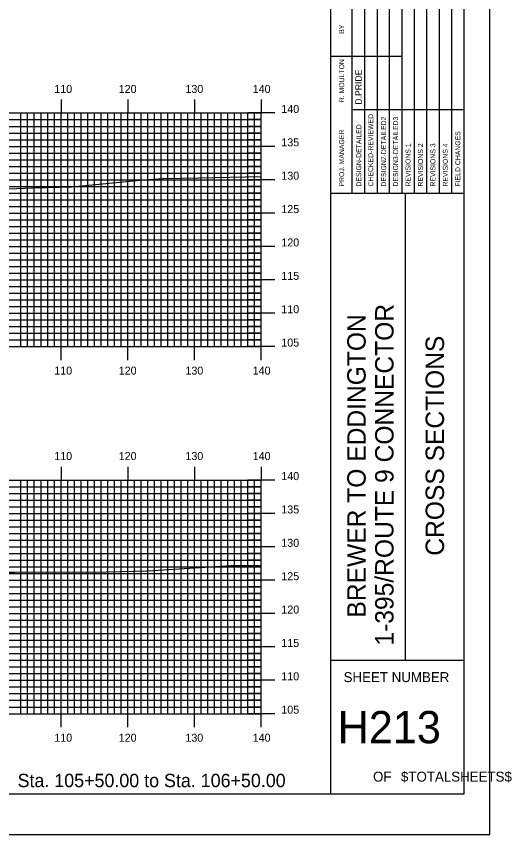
# Model space of a CAD drawing. Extents: x 1768087 to 1768430, y 442591 to 442811.
# Drawn here: x 1768356.3 to 1768430.5, y 442590.5 to 442713.1 of the extents above; entities that cross this region are included whole.
import ezdxf

# ---------------------------------------------------------------- set-up
doc = ezdxf.new("R2010")
doc.units = 0
for name, color, linetype in [('BORDER', 7, 'Continuous'), ('H_V ANNOTATION', 7, 'Continuous'), ('MAJOR', 7, 'Continuous'), ('MINOR', 7, 'Continuous'), ('PLOT BOUNDARY', 7, 'Continuous'), ('S_Roadway_Centerline', 7, 'Continuous')]:
    doc.layers.add(name, color=color, linetype=linetype)

msp = doc.modelspace()

# ---------------------------------------------------------------- linework, layer by layer
at = {"layer": 'BORDER'}
for p, q in [((1768403.36, 442596.67), (1768403.36, 442806.67)), ((1768403.36, 442686.67), (1768423.36, 442686.67)), ((1768414.54, 442616.67), (1768414.54, 442686.67)), ((1768403.36, 442616.67), (1768423.36, 442616.67))]:
    msp.add_line(p, q, dxfattribs=at)
msp.add_lwpolyline([(1768103.36, 442596.67), (1768423.36, 442596.67), (1768423.36, 442806.67), (1768103.36, 442806.67)], close=True, dxfattribs=at)
for points in [[(1768408.46, 442686.68), (1768408.46, 442721.67)], [(1768410.32, 442721.67), (1768410.32, 442686.68)], [(1768412.18, 442686.68), (1768412.18, 442721.67)], [(1768414.05, 442686.68), (1768414.05, 442721.67)], [(1768415.91, 442686.68), (1768415.91, 442721.67)], [(1768417.77, 442686.68), (1768417.77, 442721.67)], [(1768419.64, 442686.68), (1768419.64, 442721.67)], [(1768421.5, 442686.68), (1768421.5, 442721.67)], [(1768406.59, 442686.68), (1768406.59, 442720.26)], [(1768403.36, 442707.17), (1768406.59, 442707.17)], [(1768406.59, 442707.17), (1768414.05, 442707.17)], [(1768406.59, 442699.17), (1768423.36, 442699.17)]]:
    msp.add_lwpolyline(points, dxfattribs=at)
at = {"layer": 'MAJOR'}
for p, q in [((1768362.96, 442700.67), (1768362.96, 442698.67)), ((1768372.96, 442700.67), (1768372.96, 442698.67)), ((1768382.96, 442700.67), (1768382.96, 442698.67)), ((1768392.96, 442700.67), (1768392.96, 442698.67)), ((1768112.96, 442698.67), (1768392.96, 442698.67)), ((1768112.96, 442698.67), (1768392.96, 442698.67)), ((1768362.96, 442663.67), (1768362.96, 442698.67)), ((1768372.96, 442663.67), (1768372.96, 442698.67)), ((1768382.96, 442663.67), (1768382.96, 442698.67)), ((1768394.97, 442698.67), (1768390.96, 442698.67)), ((1768392.96, 442663.67), (1768392.96, 442698.67)), ((1768392.96, 442663.67), (1768392.96, 442698.67)), ((1768112.96, 442693.67), (1768392.96, 442693.67)), ((1768394.97, 442693.67), (1768390.96, 442693.67)), ((1768112.96, 442688.67), (1768392.96, 442688.67)), ((1768394.97, 442688.67), (1768390.96, 442688.67)), ((1768112.96, 442683.67), (1768392.96, 442683.67)), ((1768394.97, 442683.67), (1768390.96, 442683.67)), ((1768112.96, 442678.67), (1768392.96, 442678.67)), ((1768394.97, 442678.67), (1768390.96, 442678.67)), ((1768112.96, 442673.67), (1768392.96, 442673.67)), ((1768394.97, 442673.67), (1768390.96, 442673.67)), ((1768112.96, 442668.67), (1768392.96, 442668.67)), ((1768394.97, 442668.67), (1768390.96, 442668.67)), ((1768112.96, 442663.67), (1768392.96, 442663.67)), ((1768112.96, 442663.67), (1768392.96, 442663.67)), ((1768362.96, 442661.66), (1768362.96, 442663.67)), ((1768372.96, 442661.66), (1768372.96, 442663.67)), ((1768382.96, 442661.66), (1768382.96, 442663.67)), ((1768394.97, 442663.67), (1768390.96, 442663.67)), ((1768392.96, 442661.66), (1768392.96, 442663.67)), ((1768362.96, 442645.67), (1768362.96, 442643.67)), ((1768372.96, 442645.67), (1768372.96, 442643.67)), ((1768382.96, 442645.67), (1768382.96, 442643.67)), ((1768392.96, 442645.67), (1768392.96, 442643.67)), ((1768112.96, 442643.67), (1768392.96, 442643.67)), ((1768112.96, 442643.67), (1768392.96, 442643.67)), ((1768362.96, 442608.67), (1768362.96, 442643.67)), ((1768372.96, 442608.67), (1768372.96, 442643.67)), ((1768382.96, 442608.67), (1768382.96, 442643.67)), ((1768394.97, 442643.67), (1768390.96, 442643.67)), ((1768392.96, 442608.67), (1768392.96, 442643.67)), ((1768392.96, 442608.67), (1768392.96, 442643.67)), ((1768112.96, 442638.67), (1768392.96, 442638.67)), ((1768394.97, 442638.67), (1768390.96, 442638.67)), ((1768112.96, 442633.67), (1768392.96, 442633.67)), ((1768394.97, 442633.67), (1768390.96, 442633.67)), ((1768112.96, 442628.67), (1768392.96, 442628.67)), ((1768394.97, 442628.67), (1768390.96, 442628.67)), ((1768112.96, 442623.67), (1768392.96, 442623.67)), ((1768394.97, 442623.67), (1768390.96, 442623.67)), ((1768112.96, 442618.67), (1768392.96, 442618.67)), ((1768394.97, 442618.67), (1768390.96, 442618.67)), ((1768112.96, 442613.67), (1768392.96, 442613.67)), ((1768394.97, 442613.67), (1768390.96, 442613.67)), ((1768112.96, 442608.67), (1768392.96, 442608.67)), ((1768112.96, 442608.67), (1768392.96, 442608.67)), ((1768362.96, 442606.66), (1768362.96, 442608.67)), ((1768372.96, 442606.66), (1768372.96, 442608.67)), ((1768382.96, 442606.66), (1768382.96, 442608.67)), ((1768394.97, 442608.67), (1768390.96, 442608.67)), ((1768392.96, 442606.66), (1768392.96, 442608.67))]:
    msp.add_line(p, q, dxfattribs=at)
at = {"layer": 'MINOR'}
for p, q in [((1768356.96, 442663.67), (1768356.96, 442698.67)), ((1768357.96, 442663.67), (1768357.96, 442698.67)), ((1768358.96, 442663.67), (1768358.96, 442698.67)), ((1768359.96, 442663.67), (1768359.96, 442698.67)), ((1768360.96, 442663.67), (1768360.96, 442698.67)), ((1768361.96, 442663.67), (1768361.96, 442698.67)), ((1768363.96, 442663.67), (1768363.96, 442698.67)), ((1768364.96, 442663.67), (1768364.96, 442698.67)), ((1768365.96, 442663.67), (1768365.96, 442698.67)), ((1768366.96, 442663.67), (1768366.96, 442698.67)), ((1768367.96, 442663.67), (1768367.96, 442698.67)), ((1768368.96, 442663.67), (1768368.96, 442698.67)), ((1768369.96, 442663.67), (1768369.96, 442698.67)), ((1768370.96, 442663.67), (1768370.96, 442698.67)), ((1768371.96, 442663.67), (1768371.96, 442698.67)), ((1768373.96, 442663.67), (1768373.96, 442698.67)), ((1768374.96, 442663.67), (1768374.96, 442698.67)), ((1768375.96, 442663.67), (1768375.96, 442698.67)), ((1768376.96, 442663.67), (1768376.96, 442698.67)), ((1768377.96, 442663.67), (1768377.96, 442698.67)), ((1768378.96, 442663.67), (1768378.96, 442698.67)), ((1768379.96, 442663.67), (1768379.96, 442698.67)), ((1768380.96, 442663.67), (1768380.96, 442698.67)), ((1768381.96, 442663.67), (1768381.96, 442698.67)), ((1768383.96, 442663.67), (1768383.96, 442698.67)), ((1768384.96, 442663.67), (1768384.96, 442698.67)), ((1768385.96, 442663.67), (1768385.96, 442698.67)), ((1768386.96, 442663.67), (1768386.96, 442698.67)), ((1768387.96, 442663.67), (1768387.96, 442698.67)), ((1768388.96, 442663.67), (1768388.96, 442698.67)), ((1768389.96, 442663.67), (1768389.96, 442698.67)), ((1768390.96, 442663.67), (1768390.96, 442698.67)), ((1768391.96, 442663.67), (1768391.96, 442698.67)), ((1768112.96, 442697.67), (1768392.96, 442697.67)), ((1768112.96, 442696.67), (1768392.96, 442696.67)), ((1768392.96, 442697.67), (1768390.96, 442697.67)), ((1768392.96, 442696.67), (1768390.96, 442696.67)), ((1768112.96, 442695.67), (1768392.96, 442695.67)), ((1768392.96, 442695.67), (1768390.96, 442695.67)), ((1768112.96, 442694.67), (1768392.96, 442694.67)), ((1768392.96, 442694.67), (1768390.96, 442694.67)), ((1768112.96, 442692.67), (1768392.96, 442692.67)), ((1768392.96, 442692.67), (1768390.96, 442692.67)), ((1768112.96, 442691.67), (1768392.96, 442691.67)), ((1768112.96, 442690.67), (1768392.96, 442690.67)), ((1768392.96, 442691.67), (1768390.96, 442691.67)), ((1768392.96, 442690.67), (1768390.96, 442690.67)), ((1768112.96, 442689.67), (1768392.96, 442689.67)), ((1768392.96, 442689.67), (1768390.96, 442689.67)), ((1768112.96, 442687.67), (1768392.96, 442687.67)), ((1768392.96, 442687.67), (1768390.96, 442687.67)), ((1768112.96, 442686.67), (1768392.96, 442686.67)), ((1768112.96, 442685.67), (1768392.96, 442685.67)), ((1768392.96, 442686.67), (1768390.96, 442686.67)), ((1768392.96, 442685.67), (1768390.96, 442685.67)), ((1768112.96, 442684.67), (1768392.96, 442684.67)), ((1768392.96, 442684.67), (1768390.96, 442684.67)), ((1768112.96, 442682.67), (1768392.96, 442682.67)), ((1768392.96, 442682.67), (1768390.96, 442682.67)), ((1768112.96, 442681.67), (1768392.96, 442681.67)), ((1768392.96, 442681.67), (1768390.96, 442681.67)), ((1768112.96, 442680.67), (1768392.96, 442680.67)), ((1768112.96, 442679.67), (1768392.96, 442679.67)), ((1768392.96, 442680.67), (1768390.96, 442680.67)), ((1768392.96, 442679.67), (1768390.96, 442679.67)), ((1768112.96, 442677.67), (1768392.96, 442677.67)), ((1768392.96, 442677.67), (1768390.96, 442677.67)), ((1768112.96, 442676.67), (1768392.96, 442676.67)), ((1768392.96, 442676.67), (1768390.96, 442676.67)), ((1768112.96, 442675.67), (1768392.96, 442675.67)), ((1768112.96, 442674.67), (1768392.96, 442674.67)), ((1768392.96, 442675.67), (1768390.96, 442675.67)), ((1768392.96, 442674.67), (1768390.96, 442674.67)), ((1768112.96, 442672.67), (1768392.96, 442672.67)), ((1768392.96, 442672.67), (1768390.96, 442672.67)), ((1768112.96, 442671.67), (1768392.96, 442671.67)), ((1768392.96, 442671.67), (1768390.96, 442671.67)), ((1768112.96, 442670.67), (1768392.96, 442670.67)), ((1768112.96, 442669.67), (1768392.96, 442669.67)), ((1768392.96, 442670.67), (1768390.96, 442670.67)), ((1768392.96, 442669.67), (1768390.96, 442669.67)), ((1768112.96, 442667.67), (1768392.96, 442667.67)), ((1768392.96, 442667.67), (1768390.96, 442667.67)), ((1768112.96, 442666.67), (1768392.96, 442666.67)), ((1768392.96, 442666.67), (1768390.96, 442666.67)), ((1768112.96, 442665.67), (1768392.96, 442665.67)), ((1768392.96, 442665.67), (1768390.96, 442665.67)), ((1768112.96, 442664.67), (1768392.96, 442664.67)), ((1768392.96, 442664.67), (1768390.96, 442664.67)), ((1768356.96, 442608.67), (1768356.96, 442643.67)), ((1768357.96, 442608.67), (1768357.96, 442643.67)), ((1768358.96, 442608.67), (1768358.96, 442643.67)), ((1768359.96, 442608.67), (1768359.96, 442643.67)), ((1768360.96, 442608.67), (1768360.96, 442643.67)), ((1768361.96, 442608.67), (1768361.96, 442643.67)), ((1768363.96, 442608.67), (1768363.96, 442643.67)), ((1768364.96, 442608.67), (1768364.96, 442643.67)), ((1768365.96, 442608.67), (1768365.96, 442643.67)), ((1768366.96, 442608.67), (1768366.96, 442643.67)), ((1768367.96, 442608.67), (1768367.96, 442643.67)), ((1768368.96, 442608.67), (1768368.96, 442643.67)), ((1768369.96, 442608.67), (1768369.96, 442643.67)), ((1768370.96, 442608.67), (1768370.96, 442643.67)), ((1768371.96, 442608.67), (1768371.96, 442643.67)), ((1768373.96, 442608.67), (1768373.96, 442643.67)), ((1768374.96, 442608.67), (1768374.96, 442643.67)), ((1768375.96, 442608.67), (1768375.96, 442643.67)), ((1768376.96, 442608.67), (1768376.96, 442643.67)), ((1768377.96, 442608.67), (1768377.96, 442643.67)), ((1768378.96, 442608.67), (1768378.96, 442643.67)), ((1768379.96, 442608.67), (1768379.96, 442643.67)), ((1768380.96, 442608.67), (1768380.96, 442643.67)), ((1768381.96, 442608.67), (1768381.96, 442643.67)), ((1768383.96, 442608.67), (1768383.96, 442643.67)), ((1768384.96, 442608.67), (1768384.96, 442643.67)), ((1768385.96, 442608.67), (1768385.96, 442643.67)), ((1768386.96, 442608.67), (1768386.96, 442643.67)), ((1768387.96, 442608.67), (1768387.96, 442643.67)), ((1768388.96, 442608.67), (1768388.96, 442643.67)), ((1768389.96, 442608.67), (1768389.96, 442643.67)), ((1768390.96, 442608.67), (1768390.96, 442643.67)), ((1768391.96, 442608.67), (1768391.96, 442643.67)), ((1768112.96, 442642.67), (1768392.96, 442642.67)), ((1768112.96, 442641.67), (1768392.96, 442641.67)), ((1768392.96, 442642.67), (1768390.96, 442642.67)), ((1768392.96, 442641.67), (1768390.96, 442641.67)), ((1768112.96, 442640.67), (1768392.96, 442640.67)), ((1768392.96, 442640.67), (1768390.96, 442640.67)), ((1768112.96, 442639.67), (1768392.96, 442639.67)), ((1768392.96, 442639.67), (1768390.96, 442639.67)), ((1768112.96, 442637.67), (1768392.96, 442637.67)), ((1768112.96, 442636.67), (1768392.96, 442636.67)), ((1768392.96, 442637.67), (1768390.96, 442637.67)), ((1768392.96, 442636.67), (1768390.96, 442636.67)), ((1768112.96, 442635.67), (1768392.96, 442635.67)), ((1768392.96, 442635.67), (1768390.96, 442635.67)), ((1768112.96, 442634.67), (1768392.96, 442634.67)), ((1768392.96, 442634.67), (1768390.96, 442634.67)), ((1768112.96, 442632.67), (1768392.96, 442632.67)), ((1768112.96, 442631.67), (1768392.96, 442631.67)), ((1768392.96, 442632.67), (1768390.96, 442632.67)), ((1768392.96, 442631.67), (1768390.96, 442631.67)), ((1768112.96, 442630.67), (1768392.96, 442630.67)), ((1768392.96, 442630.67), (1768390.96, 442630.67)), ((1768112.96, 442629.67), (1768392.96, 442629.67)), ((1768392.96, 442629.67), (1768390.96, 442629.67)), ((1768112.96, 442627.67), (1768392.96, 442627.67)), ((1768392.96, 442627.67), (1768390.96, 442627.67)), ((1768112.96, 442626.67), (1768392.96, 442626.67)), ((1768112.96, 442625.67), (1768392.96, 442625.67)), ((1768392.96, 442626.67), (1768390.96, 442626.67)), ((1768392.96, 442625.67), (1768390.96, 442625.67)), ((1768112.96, 442624.67), (1768392.96, 442624.67)), ((1768392.96, 442624.67), (1768390.96, 442624.67)), ((1768112.96, 442622.67), (1768392.96, 442622.67)), ((1768392.96, 442622.67), (1768390.96, 442622.67)), ((1768112.96, 442621.67), (1768392.96, 442621.67)), ((1768112.96, 442620.67), (1768392.96, 442620.67)), ((1768392.96, 442621.67), (1768390.96, 442621.67)), ((1768392.96, 442620.67), (1768390.96, 442620.67)), ((1768112.96, 442619.67), (1768392.96, 442619.67)), ((1768392.96, 442619.67), (1768390.96, 442619.67)), ((1768112.96, 442617.67), (1768392.96, 442617.67)), ((1768392.96, 442617.67), (1768390.96, 442617.67)), ((1768112.96, 442616.67), (1768392.96, 442616.67)), ((1768392.96, 442616.67), (1768390.96, 442616.67)), ((1768112.96, 442615.67), (1768392.96, 442615.67)), ((1768112.96, 442614.67), (1768392.96, 442614.67)), ((1768392.96, 442615.67), (1768390.96, 442615.67)), ((1768392.96, 442614.67), (1768390.96, 442614.67)), ((1768112.96, 442612.67), (1768392.96, 442612.67)), ((1768392.96, 442612.67), (1768390.96, 442612.67)), ((1768112.96, 442611.67), (1768392.96, 442611.67)), ((1768392.96, 442611.67), (1768390.96, 442611.67)), ((1768112.96, 442610.67), (1768392.96, 442610.67)), ((1768112.96, 442609.67), (1768392.96, 442609.67)), ((1768392.96, 442610.67), (1768390.96, 442610.67)), ((1768392.96, 442609.67), (1768390.96, 442609.67))]:
    msp.add_line(p, q, dxfattribs=at)
at = {"layer": 'PLOT BOUNDARY'}
msp.add_lwpolyline([(1768087.18, 442590.55), (1768427.18, 442590.55), (1768427.18, 442810.55), (1768087.18, 442810.55)], close=True, dxfattribs=at)
at = {"layer": 'S_Roadway_Centerline'}
for points in [[(1768282.89, 442691.98), (1768286.37, 442691.56), (1768302.48, 442689.93), (1768306.27, 442689.13), (1768312.14, 442688.53), (1768320.63, 442687.59), (1768329.2, 442687.64), (1768339.81, 442687.35), (1768343.04, 442687.3), (1768352.58, 442687.2), (1768358.72, 442687.45), (1768364.56, 442687.62), (1768374.74, 442688.6), (1768378.21, 442688.85), (1768383.6, 442688.96), (1768392.96, 442689.16)], [(1768269.05, 442637.11), (1768292.69, 442636.71), (1768293.14, 442636.7), (1768293.42, 442636.69), (1768305.45, 442635.69), (1768313.49, 442634.47), (1768324.22, 442632.98), (1768330.96, 442631.85), (1768340.46, 442630.49), (1768351.07, 442629.88), (1768352.98, 442629.85), (1768356.04, 442629.88), (1768369.7, 442629.91), (1768375.96, 442630.07), (1768387.64, 442630.81), (1768388.44, 442630.87), (1768390.75, 442630.86), (1768392.96, 442630.87)]]:
    msp.add_lwpolyline(points, dxfattribs=at)

# ---------------------------------------------------------------- texts
at = {"layer": 'BORDER'}
for s, height, p in [('BY', 0.743, (1768405.37, 442710.54)), ('R. MOULTON', 0.745, (1768405.37, 442700.28)), ('D.PRIDE', 0.969, (1768408.01, 442699.92)), ('CHECKED-REVIEWED', 0.7455, (1768409.72, 442687.65)), ('DESIGN-DETAILED', 0.7455, (1768407.94, 442687.65)), ('DESIGN2-DETAILED2', 0.7455, (1768411.66, 442687.65)), ('DESIGN3-DETAILED3', 0.7455, (1768413.45, 442687.65)), ('PROJ. MANAGER', 0.7455, (1768405.37, 442687.65)), ('FIELD CHANGES', 0.7455, (1768422.77, 442687.65)), ('REVISIONS 1', 0.7455, (1768415.31, 442687.65)), ('REVISIONS 2', 0.7455, (1768417.18, 442687.65)), ('REVISIONS 3', 0.7455, (1768419.04, 442687.65)), ('REVISIONS 4', 0.7455, (1768420.9, 442687.65)), ('1-395/ROUTE 9 CONNECTOR', 2.7557, (1768412.77, 442618.87)), ('BREWER TO EDDINGTON', 2.7557, (1768408.59, 442623.07)), ('CROSS SECTIONS', 2.7557, (1768420.33, 442632.34))]:
    msp.add_text(s, height=height, rotation=90, dxfattribs=at).set_placement(p)
for s, height, p in [('SHEET NUMBER', 1.4905, (1768405.29, 442613.4)), ('H213', 4.839, (1768404.39, 442604.23)), ('OF', 1.491, (1768409.7, 442598.49)), ('$TOTALSHEETS$', 1.4905, (1768413.88, 442598.49))]:
    msp.add_text(s, height=height, dxfattribs=at).set_placement(p)
at = {"layer": 'H_V ANNOTATION'}
for s, height, p in [('110', 1.2, (1768361.95, 442701.67)), ('120', 1.2, (1768371.6, 442701.67)), ('130', 1.2, (1768381.59, 442701.67)), ('140', 1.2, (1768391.67, 442701.67)), ('140', 1.2, (1768395.96, 442698.67)), ('135', 1.2, (1768395.96, 442693.67)), ('130', 1.2, (1768395.96, 442688.67)), ('125', 1.2, (1768395.96, 442683.67)), ('120', 1.2, (1768395.96, 442678.67)), ('115', 1.2, (1768395.96, 442673.67)), ('110', 1.2, (1768395.96, 442668.67)), ('105', 1.2, (1768395.96, 442663.67)), ('110', 1.2, (1768361.95, 442659.47)), ('120', 1.2, (1768371.6, 442659.47)), ('130', 1.2, (1768381.59, 442659.47)), ('140', 1.2, (1768391.67, 442659.47)), ('110', 1.2, (1768361.95, 442646.67)), ('120', 1.2, (1768371.6, 442646.67)), ('130', 1.2, (1768381.59, 442646.67)), ('140', 1.2, (1768391.67, 442646.67)), ('140', 1.2, (1768395.96, 442643.67)), ('135', 1.2, (1768395.96, 442638.67)), ('130', 1.2, (1768395.96, 442633.67)), ('125', 1.2, (1768395.96, 442628.67)), ('120', 1.2, (1768395.96, 442623.67)), ('115', 1.2, (1768395.96, 442618.67)), ('110', 1.2, (1768395.96, 442613.67)), ('105', 1.2, (1768395.96, 442608.67)), ('110', 1.2, (1768361.95, 442604.47)), ('120', 1.2, (1768371.6, 442604.47)), ('130', 1.2, (1768381.59, 442604.47)), ('140', 1.2, (1768391.67, 442604.47)), ('Sta. 105+50.00 to Sta. 106+50.00', 2.0004, (1768356.45, 442597.66))]:
    msp.add_text(s, height=height, dxfattribs=at).set_placement(p)

doc.saveas('drawing.dxf')
